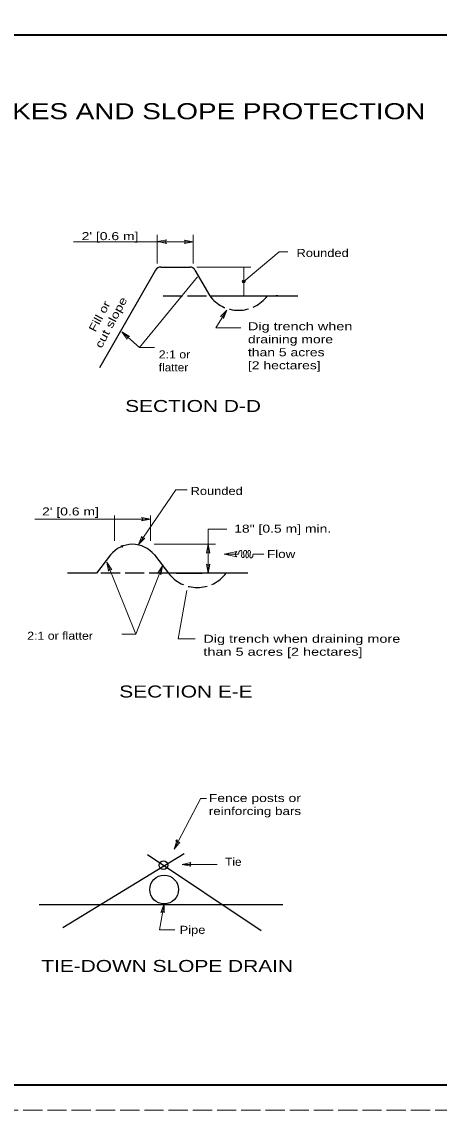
# Model space of a CAD drawing. Extents: x 1043.1 to 1101.1, y 672.4 to 716.4.
# Drawn here: x 1057.15 to 1065.49, y 672.4 to 694.15 of the extents above; entities that cross this region are included whole.
import ezdxf
from ezdxf.enums import TextEntityAlignment as Align

# ---------------------------------------------------------------- set-up
doc = ezdxf.new("R2010")
doc.units = 0
doc.header["$LTSCALE"] = 0.064
doc.header["$PDMODE"] = 32
doc.header["$PDSIZE"] = 0.032
doc.linetypes.add('LONG_DASHED', pattern=[7.5, 6, -1.5])
doc.layers.add('1', color=7, linetype='Continuous', lineweight=13)

msp = doc.modelspace()

# ---------------------------------------------------------------- hatches: boundary and pattern name
at = {"layer": '1'}
msp.add_hatch(color=256, dxfattribs=at).paths.add_polyline_path([(1061.61298, 688.96125, 1), (1061.55634, 688.96125, 1)])

# ---------------------------------------------------------------- linework, layer by layer
at = {"layer": '1', "lineweight": 25}
for p, q in [((1045.14425, 693.89508), (1076.64425, 693.89508)), ((1059.82292, 689.18867), (1058.70617, 687.23433)), ((1059.92717, 689.24917), (1060.5075, 689.24917)), ((1060.61175, 689.18867), (1060.906, 688.67342)), ((1060.906, 688.67342), (1062.664, 688.67342)), ((1062.26367, 688.67342), (1062.22517, 688.67342)), ((1058.9265, 683.49892), (1058.64367, 683.13208)), ((1059.80017, 683.49892), (1060.08292, 683.13208)), ((1059.9645, 683.28567), (1060.056, 683.16683)), ((1058.64367, 683.13208), (1058.06792, 683.13208)), ((1061.66625, 683.13208), (1060.08292, 683.13208)), ((1060.23792, 683.13208), (1060.75275, 683.13208)), ((1057.97125, 676.04483), (1060.39708, 677.52383)), ((1059.665, 677.5095), (1061.93292, 675.98742)), ((1057.49758, 676.50433), (1062.36358, 676.50433))]:
    msp.add_line(p, q, dxfattribs=at)
at = {"layer": '1', "lineweight": 40}
msp.add_line((1045.14425, 693.89508), (1076.64425, 693.89508), dxfattribs=at)
msp.add_line((1045.14425, 693.89508), (1076.64425, 693.89508), dxfattribs=at)
at = {"layer": '1'}
for p, q in [((1060.57717, 689.75275), (1058.182, 689.75275)), ((1059.8575, 689.32092), (1059.8575, 689.89667)), ((1060.57717, 689.32092), (1060.57717, 689.89667)), ((1061.58467, 688.96125), (1062.29117, 689.55667)), ((1062.29117, 689.55667), (1062.46883, 689.55667)), ((1060.64917, 689.24917), (1061.7285, 689.24917)), ((1061.58467, 689.24917), (1061.58467, 688.67342)), ((1061.58467, 688.99558), (1061.58467, 688.99542)), ((1059.504, 687.64058), (1059.80383, 687.64058)), ((1059.72317, 684.21125), (1057.40942, 684.21125)), ((1059.0035, 684.28183), (1059.0035, 683.77958)), ((1059.72317, 684.28183), (1059.72317, 683.77958)), ((1060.8745, 684.00908), (1060.8745, 683.13208)), ((1060.8745, 684.00908), (1061.24842, 684.00908)), ((1061.01842, 683.70767), (1059.795, 683.70767)), ((1061.19525, 683.5115), (1061.48317, 683.511)), ((1061.77108, 683.51067), (1061.987, 683.51042)), ((1059.4275, 681.91142), (1059.14983, 681.91142)), ((1060.72675, 678.63008), (1060.19558, 677.61058)), ((1060.72958, 678.62917), (1060.842, 678.62917)), ((1060.354, 677.3085), (1061.05733, 677.3085))]:
    msp.add_line(p, q, dxfattribs=at)
at = {"layer": '1', "linetype": 'LONG_DASHED', "lineweight": 25}
for p, q in [((1059.97533, 688.67342), (1060.90592, 688.67342)), ((1060.08292, 683.13208), (1058.64367, 683.13208))]:
    msp.add_line(p, q, dxfattribs=at)
at = {"layer": '1', "linetype": 'LONG_DASHED'}
msp.add_lwpolyline([(1043.14425, 672.39508), (1077.14425, 672.39508), (1077.14425, 694.39508), (1043.14425, 694.39508)], close=True, dxfattribs=at)
at = {"layer": '1', "lineweight": 25}
msp.add_lwpolyline([(1076.64425, 672.89508), (1045.14425, 672.89508), (1045.14425, 693.89508)], dxfattribs=at)
at = {"layer": '1', "lineweight": 40}
msp.add_lwpolyline([(1076.64425, 672.89508), (1045.14425, 672.89508), (1045.14425, 693.89508)], dxfattribs=at)
msp.add_lwpolyline([(1076.64425, 672.89508), (1045.14425, 672.89508), (1045.14425, 693.89508)], dxfattribs=at)
at = {"layer": '1'}
for points in [[(1060.045, 689.72217), (1059.8685, 689.75742), (1060.045, 689.79275), (1060.045, 689.79267)], [(1060.40058, 689.78808), (1060.57717, 689.75275), (1060.40058, 689.7175), (1060.40058, 689.71758)], [(1059.14867, 687.95283), (1059.504, 687.64058), (1060.65883, 689.05683)], [(1061.24733, 688.39025), (1061.02525, 688.03625), (1061.525, 688.03625)], [(1061.12367, 688.2595), (1061.24733, 688.39025), (1061.1835, 688.222), (1061.18342, 688.222)], [(1059.258, 687.80983), (1059.14867, 687.95283), (1059.30458, 687.86283), (1059.3045, 687.86283)], [(1059.483, 683.70283), (1060.22692, 684.79642), (1060.45275, 684.79642)], [(1059.54667, 684.176), (1059.72317, 684.21125), (1059.54667, 684.24658), (1059.54667, 684.2465)], [(1059.55317, 683.86858), (1059.483, 683.70283), (1059.6115, 683.82892), (1059.61142, 683.82892)], [(1060.90983, 683.53108), (1060.8745, 683.70767), (1060.83917, 683.53108), (1060.83925, 683.53108)], [(1061.4495, 683.46025), (1061.19525, 683.5115), (1061.44958, 683.56192), (1061.44958, 683.56175)], [(1059.9605, 683.27583), (1059.4275, 681.91142), (1058.85, 683.34875)], [(1058.9485, 683.19808), (1058.85, 683.34875), (1058.883, 683.17183), (1058.88308, 683.17183)], [(1059.92908, 683.09858), (1059.9605, 683.27583), (1059.86333, 683.12425), (1059.86342, 683.12425)], [(1060.83917, 683.30867), (1060.8745, 683.13208), (1060.90983, 683.30867), (1060.90967, 683.30867)], [(1060.45, 682.78183), (1060.2785, 681.81625), (1060.61858, 681.81625)], [(1060.30842, 677.75083), (1060.19558, 677.61058), (1060.24583, 677.78342)], [(1060.53058, 677.34383), (1060.354, 677.3085), (1060.53058, 677.27325), (1060.53058, 677.27333)], [(1059.99525, 676.51842), (1059.90467, 676.00083), (1060.20967, 676.00083)], [(1059.99908, 676.3385), (1059.99525, 676.51842), (1059.92958, 676.35083), (1059.92967, 676.35083)]]:
    msp.add_lwpolyline(points, dxfattribs=at)
msp.add_circle((1061.58466, 688.96125), 0.02832, dxfattribs=at)
at = {"layer": '1', "lineweight": 25}
for centre, radius in [((1059.98083, 677.29417), 0.08727), ((1059.99522, 676.80595), 0.28752)]:
    msp.add_circle(centre, radius, dxfattribs=at)
at = {"layer": '1'}
for centre, radius, start, end in [((1060.05935, 689.75738), 0.03811, 112.08789, 247.91402), ((1060.38626, 689.75286), 0.03811, 292.08789, 67.91402), ((1061.14588, 688.2286), 0.03811, 349.98562, 125.81174), ((1059.29201, 687.82683), 0.03811, 70.78042, 206.60655), ((1059.53229, 684.21122), 0.03811, 292.08598, 67.91211), ((1059.59029, 683.86065), 0.03811, 167.86025, 303.68638), ((1060.87451, 683.51676), 0.03811, 22.08598, 157.91211), ((1061.47021, 683.51091), 0.05488, 111.99319, 247.81932), ((1058.92115, 683.17167), 0.03811, 43.97554, 179.80167), ((1060.87439, 683.32298), 0.03811, 202.08598, 337.91211), ((1059.89106, 683.09805), 0.03811, 0.74822, 136.57435), ((1060.2838, 677.77982), 0.03811, 174.5682, 310.39433), ((1060.54488, 677.30861), 0.03811, 112.08598, 247.91211), ((1059.96188, 676.3305), 0.03811, 12.01346, 147.83959)]:
    msp.add_arc(centre, radius, start, end, dxfattribs=at)
at = {"layer": '1', "lineweight": 25}
for centre, major_axis, start_param, end_param in [((1059.9271, 689.12915), (-0.11994, 0), 4.71238898, 5.76372345), ((1060.50758, 689.12915), (0.11994, 0), 0.51940809, 1.57079633), ((1059.36327, 683.1463), (0.56138, 0), 0.67925815, 2.46233451)]:
    msp.add_ellipse(centre, major_axis=major_axis, ratio=0.999895, start_param=start_param, end_param=end_param, dxfattribs=at)
at = {"layer": '1', "linetype": 'LONG_DASHED', "lineweight": 25}
for centre, major_axis, start_param, end_param in [((1061.48176, 689.10516), (-0.71964, 0), 0.64341786, 2.49809155), ((1060.65862, 683.5637), (0.71964, 0), 3.78509375, 5.63968421)]:
    msp.add_ellipse(centre, major_axis=major_axis, ratio=0.999895, start_param=start_param, end_param=end_param, dxfattribs=at)
at = {"layer": '1'}
msp.add_spline([(1061.48317, 683.511), (1061.50775, 683.57667), (1061.538, 683.58067), (1061.55567, 683.445), (1061.58342, 683.44192), (1061.59175, 683.5775), (1061.63008, 683.58717), (1061.64208, 683.44017), (1061.66658, 683.44092), (1061.68067, 683.58133), (1061.70842, 683.58217), (1061.71717, 683.43842), (1061.74158, 683.43925), (1061.77108, 683.51067)], degree=3, dxfattribs=at)
for p in [(1059.15425, 683.66725), (1060.24583, 677.78342)]:
    msp.add_point(p, dxfattribs=at)

# ---------------------------------------------------------------- texts
at = {"layer": '1', "width": 1.3}
for s, height, p in [('DIKES AND SLOPE PROTECTION', 0.32, (1060.81029, 692.20542)), ("2' [0.6 m]", 0.16, (1058.91504, 689.78817)), ('SECTION D-D', 0.24, (1060.57329, 686.3525)), ("2' [0.6 m]", 0.16, (1058.1245, 684.28417)), ('SECTION E-E', 0.24, (1060.43146, 680.64525))]:
    msp.add_text(s, height=height, dxfattribs=at).set_placement(p, align=Align.CENTER)
at = {"layer": '1'}
for s, height, width, p in [('Rounded', 0.16, 1.2, (1062.64033, 689.45175)), ('Dig trench when', 0.16, 1.35, (1061.66908, 687.98633)), ('draining more', 0.16, 1.3, (1061.66908, 687.72633)), ('2:1 or', 0.16, 1.15, (1059.88833, 687.42433)), ('than 5 acres', 0.16, 1.3, (1061.66908, 687.46633)), ('[2 hectares]', 0.16, 1.3, (1061.66908, 687.20633)), ('flatter', 0.16, 1.1, (1059.88833, 687.16433)), ('Rounded', 0.16, 1.2, (1060.52408, 684.69408)), ('18" [0.5 m] min.', 0.16, 1.3, (1061.39475, 683.94058)), ('Flow', 0.16, 1.25, (1062.05142, 683.43417)), ('2:1 or flatter', 0.16, 1.15, (1057.26033, 681.79983)), ('Dig trench when draining more', 0.16, 1.35, (1060.77942, 681.73983)), ('than 5 acres [2 hectares]', 0.16, 1.35, (1060.77942, 681.47983)), ('Fence posts or', 0.16, 1.3, (1060.88792, 678.55558)), ('reinforcing bars', 0.16, 1.25, (1060.88783, 678.29558)), ('Tie', 0.16, 1.1, (1061.21475, 677.281)), ('Pipe', 0.16, 1.2, (1060.30583, 675.92117)), ('TIE-DOWN SLOPE DRAIN', 0.24, 1.3, (1057.54058, 675.15867))]:
    msp.add_text(s, height=height, dxfattribs=dict(at, width=width)).set_placement(p)
for s, width, p in [('cut slope', 1.3, (1059.00499, 688.10552)), ('Fill or', 1.25, (1058.77513, 688.22698))]:
    msp.add_text(s, height=0.16, rotation=62.167, dxfattribs=dict(at, width=width)).set_placement(p, align=Align.CENTER)

doc.saveas('drawing.dxf')
